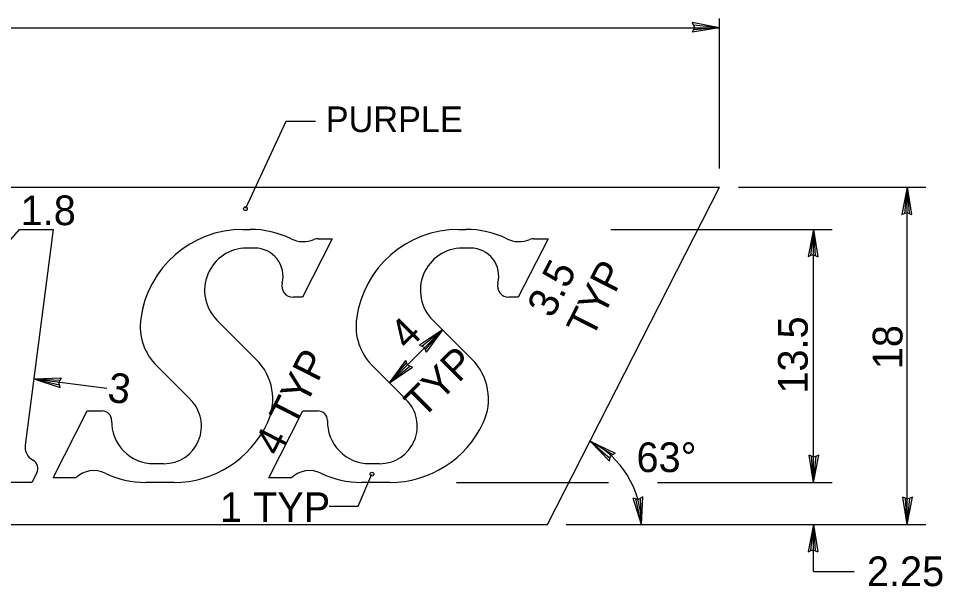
# Model space of a CAD drawing. Extents: x 10268197 to 10269179, y 2141503 to 2142677.
# Drawn here: x 10268496.1 to 10268517.89, y 2142123.05 to 2142136.46 of the extents above; entities that cross this region are included whole.
import ezdxf

# ---------------------------------------------------------------- set-up
doc = ezdxf.new("R2010")
doc.units = 0
for name, color, linetype in [('1', 7, 'Continuous'), ('52', 7, 'Continuous'), ('SOILS_SP83_SHP', 7, 'Continuous')]:
    doc.layers.add(name, color=color, linetype=linetype)

msp = doc.modelspace()

# ---------------------------------------------------------------- linework, layer by layer
at = {"layer": '1'}
for p, q in [((10268512.635, 2142132.921), (10268512.635, 2142136.461)), ((10268493.435, 2142136.24), (10268512.635, 2142136.24)), ((10268502.407, 2142134.03), (10268501.453, 2142131.972)), ((10268503.11, 2142134.03), (10268502.407, 2142134.03)), ((10268513.078, 2142132.479), (10268517.502, 2142132.479)), ((10268517.06, 2142124.515), (10268517.06, 2142132.479)), ((10268510.068, 2142131.483), (10268515.29, 2142131.483)), ((10268514.848, 2142125.51), (10268514.848, 2142131.483)), ((10268504.848, 2142127.861), (10268506.099, 2142129.113)), ((10268496.462, 2142127.958), (10268498.187, 2142127.733)), ((10268504.113, 2142124.946), (10268504.438, 2142125.705)), ((10268506.43, 2142125.51), (10268510.016, 2142125.51)), ((10268511.173, 2142125.51), (10268515.29, 2142125.51)), ((10268503.426, 2142124.946), (10268504.113, 2142124.946)), ((10268509.02, 2142124.515), (10268517.502, 2142124.515)), ((10268514.848, 2142123.409), (10268514.848, 2142124.515)), ((10268514.848, 2142123.409), (10268515.81, 2142123.409))]:
    msp.add_line(p, q, dxfattribs=at)
for centre in [(10268501.453, 2142131.971), (10268504.438, 2142125.705)]:
    msp.add_circle(centre, 0.0442, dxfattribs=at)
msp.add_arc((10268508.578, 2142124.514), 2.212, 0, 63.0012, dxfattribs=at)
at = {"layer": '52'}
for p, q in [((10268512.635, 2142136.24), (10268511.992, 2142136.364)), ((10268511.992, 2142136.364), (10268512.04, 2142136.249)), ((10268512.635, 2142136.24), (10268512.017, 2142136.304)), ((10268512.04, 2142136.249), (10268511.989, 2142136.137)), ((10268512.635, 2142136.24), (10268511.989, 2142136.137)), ((10268512.635, 2142136.24), (10268512.016, 2142136.196)), ((10268517.06, 2142132.479), (10268516.935, 2142131.836)), ((10268517.06, 2142132.479), (10268516.995, 2142131.861)), ((10268517.06, 2142132.479), (10268517.162, 2142131.832)), ((10268517.06, 2142132.479), (10268517.103, 2142131.859)), ((10268516.935, 2142131.836), (10268517.049, 2142131.883)), ((10268517.049, 2142131.883), (10268517.162, 2142131.832)), ((10268514.848, 2142131.483), (10268514.723, 2142130.84)), ((10268514.848, 2142131.483), (10268514.783, 2142130.865)), ((10268514.848, 2142131.483), (10268514.95, 2142130.836)), ((10268514.848, 2142131.483), (10268514.891, 2142130.864)), ((10268514.723, 2142130.84), (10268514.837, 2142130.888)), ((10268514.837, 2142130.888), (10268514.95, 2142130.836)), ((10268506.099, 2142129.113), (10268505.557, 2142128.746)), ((10268506.099, 2142129.113), (10268505.617, 2142128.721)), ((10268506.099, 2142129.113), (10268505.692, 2142128.644)), ((10268506.099, 2142129.113), (10268505.714, 2142128.583)), ((10268505.557, 2142128.746), (10268505.671, 2142128.699)), ((10268505.671, 2142128.699), (10268505.714, 2142128.583)), ((10268504.848, 2142127.861), (10268505.233, 2142128.391)), ((10268504.848, 2142127.861), (10268505.255, 2142128.33)), ((10268504.848, 2142127.861), (10268505.33, 2142128.253)), ((10268504.848, 2142127.861), (10268505.391, 2142128.227)), ((10268505.276, 2142128.275), (10268505.233, 2142128.391)), ((10268505.391, 2142128.227), (10268505.276, 2142128.275)), ((10268496.462, 2142127.958), (10268497.117, 2142127.976)), ((10268496.462, 2142127.958), (10268497.083, 2142127.751)), ((10268496.462, 2142127.958), (10268497.067, 2142127.814)), ((10268496.462, 2142127.958), (10268497.082, 2142127.921)), ((10268497.052, 2142127.871), (10268497.117, 2142127.976)), ((10268497.083, 2142127.751), (10268497.052, 2142127.871)), ((10268509.582, 2142126.486), (10268510.171, 2142126.199)), ((10268509.582, 2142126.486), (10268510.037, 2142126.015)), ((10268509.582, 2142126.486), (10268510.051, 2142126.079)), ((10268509.582, 2142126.486), (10268510.114, 2142126.166)), ((10268510.037, 2142126.015), (10268510.064, 2142126.137)), ((10268510.064, 2142126.137), (10268510.171, 2142126.199)), ((10268514.848, 2142125.51), (10268514.745, 2142126.157)), ((10268514.857, 2142126.106), (10268514.745, 2142126.157)), ((10268514.848, 2142125.51), (10268514.804, 2142126.13)), ((10268514.848, 2142125.51), (10268514.972, 2142126.153)), ((10268514.848, 2142125.51), (10268514.912, 2142126.129)), ((10268514.972, 2142126.153), (10268514.857, 2142126.106)), ((10268510.824, 2142125.169), (10268510.717, 2142125.107)), ((10268510.79, 2142124.515), (10268510.824, 2142125.169)), ((10268517.06, 2142124.515), (10268516.957, 2142125.162)), ((10268517.07, 2142125.111), (10268516.957, 2142125.162)), ((10268517.06, 2142124.515), (10268517.184, 2142125.158)), ((10268517.184, 2142125.158), (10268517.07, 2142125.111)), ((10268510.79, 2142124.515), (10268510.598, 2142125.141)), ((10268510.717, 2142125.107), (10268510.598, 2142125.141)), ((10268510.79, 2142124.515), (10268510.661, 2142125.123)), ((10268510.79, 2142124.515), (10268510.768, 2142125.137)), ((10268517.06, 2142124.515), (10268517.016, 2142125.134)), ((10268517.06, 2142124.515), (10268517.124, 2142125.133)), ((10268514.848, 2142124.515), (10268514.723, 2142123.872)), ((10268514.848, 2142124.515), (10268514.783, 2142123.897)), ((10268514.848, 2142124.515), (10268514.95, 2142123.868)), ((10268514.848, 2142124.515), (10268514.891, 2142123.896)), ((10268514.723, 2142123.872), (10268514.837, 2142123.919)), ((10268514.837, 2142123.919), (10268514.95, 2142123.868))]:
    msp.add_line(p, q, dxfattribs=at)
at = {"layer": 'SOILS_SP83_SHP'}
for p, q in [((10268487.397, 2142132.479), (10268512.635, 2142132.479)), ((10268508.578, 2142124.515), (10268512.635, 2142132.479)), ((10268491.607, 2142126.287), (10268496.125, 2142131.483)), ((10268496.125, 2142131.483), (10268496.921, 2142131.483)), ((10268496.921, 2142131.483), (10268496.259, 2142126.392)), ((10268501.396, 2142131.483), (10268501.564, 2142131.483)), ((10268506.484, 2142131.483), (10268506.652, 2142131.483)), ((10268503.501, 2142131.262), (10268502.798, 2142129.882)), ((10268503.169, 2142131.262), (10268503.501, 2142131.262)), ((10268508.589, 2142131.262), (10268507.886, 2142129.882)), ((10268508.257, 2142131.262), (10268508.589, 2142131.262)), ((10268501.676, 2142131.041), (10268501.487, 2142131.041)), ((10268506.764, 2142131.041), (10268506.574, 2142131.041)), ((10268502.798, 2142129.882), (10268502.577, 2142129.882)), ((10268507.886, 2142129.882), (10268507.664, 2142129.882)), ((10268500.783, 2142129.341), (10268501.71, 2142128.414)), ((10268505.871, 2142129.341), (10268506.798, 2142128.414)), ((10268500.157, 2142127.464), (10268499.362, 2142128.259)), ((10268505.246, 2142127.464), (10268504.45, 2142128.259)), ((10268496.918, 2142125.621), (10268497.721, 2142127.198)), ((10268497.721, 2142127.198), (10268498.077, 2142127.198)), ((10268502.006, 2142125.621), (10268502.809, 2142127.198)), ((10268502.809, 2142127.198), (10268503.165, 2142127.198)), ((10268499.293, 2142125.953), (10268499.532, 2142125.953)), ((10268504.381, 2142125.953), (10268504.619, 2142125.953)), ((10268496.536, 2142125.738), (10268496.419, 2142125.51)), ((10268497.456, 2142125.621), (10268496.918, 2142125.621)), ((10268502.543, 2142125.621), (10268502.006, 2142125.621)), ((10268496.419, 2142125.51), (10268494.207, 2142125.51)), ((10268499.77, 2142125.51), (10268499.104, 2142125.51)), ((10268504.858, 2142125.51), (10268504.192, 2142125.51)), ((10268486.81, 2142124.515), (10268508.578, 2142124.515))]:
    msp.add_line(p, q, dxfattribs=at)
for centre, radius, start, end in [((10268501.396, 2142129.049), 2.433, 90, 172.3089), ((10268501.564, 2142129.27), 2.212, 64.0896, 90), ((10268506.484, 2142129.049), 2.433, 90, 172.3089), ((10268506.652, 2142129.27), 2.212, 64.0896, 90), ((10268502.82, 2142131.857), 0.664, 244.0896, 292.0347), ((10268503.169, 2142130.996), 0.265, 90, 112.0347), ((10268507.908, 2142131.857), 0.664, 244.0896, 292.0347), ((10268508.257, 2142130.996), 0.265, 90, 112.0347), ((10268501.486, 2142130.045), 0.995, 90, 225), ((10268501.676, 2142130.377), 0.664, 345.6915, 90), ((10268506.574, 2142130.045), 0.995, 90, 225), ((10268506.764, 2142130.377), 0.664, 345.6915, 90), ((10268502.577, 2142130.147), 0.265, 165.6915, 270), ((10268507.664, 2142130.147), 0.265, 165.6915, 270), ((10268500.3, 2142129.197), 1.327, 172.3089, 225), ((10268505.388, 2142129.197), 1.327, 172.3089, 225), ((10268500.771, 2142127.475), 1.327, 334.95, 45), ((10268505.859, 2142127.475), 1.327, 334.95, 45), ((10268499.532, 2142126.837), 0.885, 270, 45), ((10268504.62, 2142126.837), 0.885, 270, 45), ((10268498.077, 2142126.976), 0.221, 358.6664, 90), ((10268503.165, 2142126.976), 0.221, 358.6664, 90), ((10268499.293, 2142126.948), 0.995, 178.6665, 270), ((10268499.769, 2142127.943), 2.433, 270, 334.95), ((10268504.381, 2142126.948), 0.995, 178.6665, 270), ((10268504.857, 2142127.943), 2.433, 270, 334.95), ((10268496.61, 2142126.346), 0.354, 172.5884, 241.8673), ((10268496.339, 2142125.838), 0.221, 332.9784, 61.8673), ((10268497.879, 2142125.169), 0.619, 64.3795, 133.1892), ((10268499.104, 2142127.722), 2.212, 244.3795, 270), ((10268502.967, 2142125.169), 0.619, 64.3795, 133.1892), ((10268504.192, 2142127.722), 2.212, 244.3795, 270)]:
    msp.add_arc(centre, radius, start, end, dxfattribs=at)

# ---------------------------------------------------------------- texts
at = {"layer": '1'}
for s, height, p in [('PURPLE', 0.6037, (10268503.349, 2142133.779)), ('1.8', 0.7, (10268496.153, 2142131.582)), ('63°', 0.7, (10268510.676, 2142125.754)), ('1 TYP', 0.7, (10268500.851, 2142124.575)), ('2.25', 0.7, (10268516.11, 2142123.062))]:
    msp.add_text(s, height=height, dxfattribs=at).set_placement(p)
for s, rotation, p in [('3.5', 63, (10268508.689, 2142129.36)), ('TYP', 63, (10268509.625, 2142128.883)), ('4', 45, (10268505.283, 2142128.606)), ('13.5', 90, (10268514.714, 2142127.606)), ('18', 90, (10268516.948, 2142128.182)), ('TYP', 45, (10268505.632, 2142126.994)), ('4 TYP', 62.9993, (10268502.258, 2142126.093)), ('3', 352.5994, (10268498.18, 2142127.42))]:
    msp.add_text(s, height=0.7, rotation=rotation, dxfattribs=at).set_placement(p)

doc.saveas('drawing.dxf')
